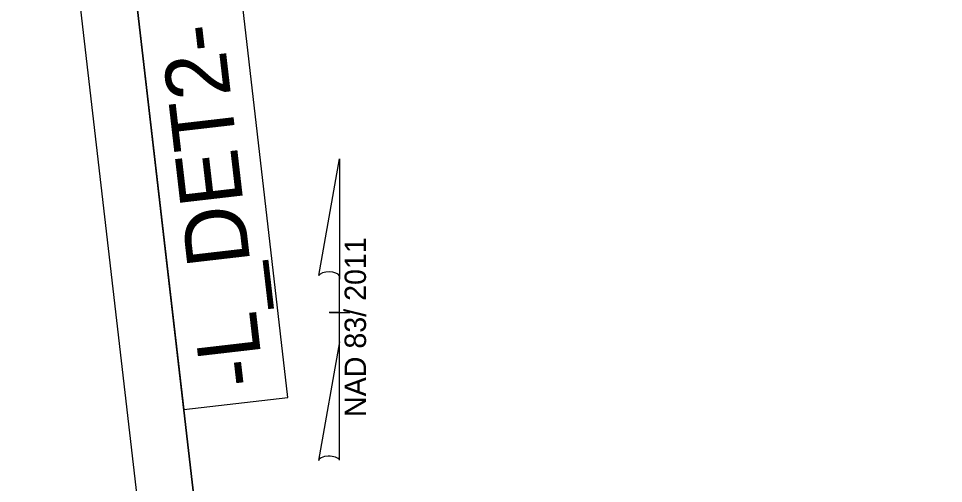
# Model space of a CAD drawing. Extents: x 477709 to 478991, y 494339 to 496137.
# Drawn here: x 477709.2 to 478076.8, y 495610.2 to 495794.9 of the extents above; entities that cross this region are included whole.
import ezdxf

# ---------------------------------------------------------------- set-up
doc = ezdxf.new("R2010")
doc.units = 0
for name, color, linetype in [('Old_Level_1', 7, 'Continuous'), ('Prop Grid Mask', 7, 'Continuous'), ('Prop North Arrow NAD83 for Plan Sheets CELL', 7, 'Continuous'), ('Sheet Layout Plan Border', 7, 'Continuous'), ('Sheet North Arrow Point CELL', 7, 'Continuous'), ('Sheet Plan CELL', 7, 'Continuous'), ('Sheet Plot Border Outside CELL', 7, 'Continuous')]:
    doc.layers.add(name, color=color, linetype=linetype)

msp = doc.modelspace()

# ---------------------------------------------------------------- linework, layer by layer
at = {"layer": 'Prop Grid Mask'}
msp.add_lwpolyline([(477756.47, 495798.38), (477774.86, 495639.58), (477816.29, 495644.38), (477797.9, 495803.18)], close=True, dxfattribs=at)
at = {"layer": 'Prop North Arrow NAD83 for Plan Sheets CELL'}
for p, q in [((477828.52, 495692.81), (477836.72, 495739.16)), ((477836.77, 495739.16), (477836.72, 495739.16)), ((477836.77, 495739.16), (477836.72, 495739.16)), ((477836.77, 495739.16), (477836.77, 495691.36)), ((477836.77, 495666.56), (477836.77, 495692.76)), ((477836.77, 495691.36), (477836.77, 495692.71)), ((477832.77, 495678.16), (477832.72, 495678.16)), ((477836.32, 495678.16), (477832.77, 495678.16)), ((477832.82, 495678.16), (477840.82, 495678.16)), ((477836.77, 495666.56), (477828.42, 495619.31)), ((477836.82, 495619.51), (477836.77, 495666.56))]:
    msp.add_line(p, q, dxfattribs=at)
for centre, start_param, end_param in [((477832.66, 495692.32), 0.216388, 2.908219), ((477832.66, 495619.15), 0.201328, 3.141593)]:
    msp.add_ellipse(centre, major_axis=(4.23, -0.03), ratio=0.461098, start_param=start_param, end_param=end_param, dxfattribs=at)
at = {"layer": 'Sheet Layout Plan Border'}
msp.add_lwpolyline([(478949.1, 494627.88), (478796.11, 495948.5), (478716.64, 495939.3), (478594.25, 496053.42), (478083.65, 495972.61), (477905.87, 496017.08), (477928.89, 495818.37), (477756.47, 495798.38), (477906.07, 494507.06)], close=True, dxfattribs=at)
at = {"layer": 'Sheet North Arrow Point CELL'}
msp.add_line((477836.77, 495739.16), (477836.77, 495739.16), dxfattribs=at)
at = {"layer": 'Sheet Plan CELL'}
for points in [[(477733.47, 495997.13), (477906.07, 494507.06), (478949.1, 494627.88), (478776.5, 496117.93)], [(478949.1, 494627.88), (477906.1, 494507.04), (477756.48, 495798.39), (477905.54, 495815.66), (477882.54, 496014.37), (478776.5, 496117.93)]]:
    msp.add_lwpolyline(points, close=True, dxfattribs=at)
at = {"layer": 'Sheet Plot Border Outside CELL'}
msp.add_lwpolyline([(478990.62, 494465.09), (478796.9, 496137.4), (477709.18, 496011.41), (477902.89, 494339.09)], close=True, dxfattribs=at)

# ---------------------------------------------------------------- texts
at = {"layer": 'Old_Level_1'}
msp.add_text('-L_DET2-', height=25, rotation=96.6074, dxfattribs=at).set_placement((477806.92, 495649.9))
at = {"layer": 'Prop North Arrow NAD83 for Plan Sheets CELL'}
msp.add_text('NAD 83/ 2011', height=8.5, rotation=90, dxfattribs=at).set_placement((477847.29, 495636.65))

doc.saveas('drawing.dxf')
